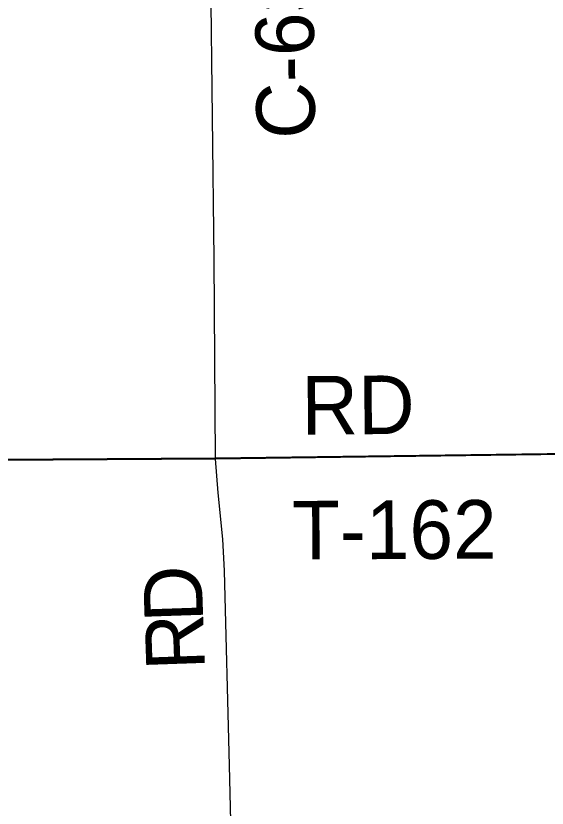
# Model space of a CAD drawing. Extents: x 0 to 34, y 0 to 22.
# Drawn here: x 6.756 to 7.272, y 14.874 to 15.642 of the extents above; entities that cross this region are included whole.
import ezdxf

# ---------------------------------------------------------------- set-up
doc = ezdxf.new("R2010")
doc.units = 0
for name, color, linetype in [('GM_X_Corporation', 7, 'Continuous'), ('GM_X_County_Road', 7, 'Continuous'), ('GM_X_County_Road_Text', 7, 'Continuous'), ('GM_X_Township_Road', 7, 'Continuous'), ('GM_X_Township_Road_Text', 7, 'Continuous')]:
    doc.layers.add(name, color=color, linetype=linetype)

msp = doc.modelspace()

# ---------------------------------------------------------------- linework, layer by layer
at = {"layer": 'GM_X_Corporation'}
msp.add_lwpolyline([(5.90994, 15.72564), (5.90994, 15.21376), (6.10258, 15.21454), (6.73943, 15.21199), (6.94963, 15.21339), (8.01532, 15.22729), (7.992, 16.45338)], dxfattribs=at)
msp.add_lwpolyline([(3.69009, 15.2048), (3.5209, 15.20411), (2.73663, 15.2014), (2.74225, 14.8151), (2.77525, 14.15375), (2.77611, 14.09996), (8.03831, 14.09996), (8.03504, 14.24979), (8.03488, 14.25722), (8.02966, 14.49633), (8.02618, 14.65547), (8.01532, 15.22729), (6.94963, 15.21339), (6.73943, 15.21199), (6.10258, 15.21454), (5.90994, 15.21376), (5.90994, 15.00852), (3.69009, 15.00852)], close=True, dxfattribs=at)
at = {"layer": 'GM_X_County_Road'}
for points in [[(6.94984, 15.21284), (6.94865, 15.40616), (6.94358, 15.81937), (6.93852, 16.22879), (6.93693, 16.45059), (6.93074, 16.82013), (6.92886, 17.07212)], [(7.0323, 14.09996), (6.98358, 14.22946), (6.97398, 14.46889), (6.9636, 14.91548), (6.95861, 15.10423), (6.95708, 15.13499), (6.95252, 15.1798), (6.94984, 15.21284)]]:
    msp.add_lwpolyline(points, dxfattribs=at)
at = {"layer": 'GM_X_Township_Road'}
msp.add_line((6.94984, 15.21284), (8.01553, 15.22674), dxfattribs=at)
msp.add_lwpolyline([(6.71506, 15.2201), (6.7165, 15.21866), (6.72295, 15.2141), (6.73964, 15.21144), (6.94984, 15.21284)], dxfattribs=at)

# ---------------------------------------------------------------- texts
at = {"layer": 'GM_X_County_Road_Text'}
for s, height, rotation, p in [('C-63', 0.056818, 90.68578, (7.04657, 15.52324)), ('D', 0.05682, 91.93101, (6.93804, 15.0554)), ('R', 0.05682, 92.00655, (6.93967, 15.00878))]:
    msp.add_text(s, height=height, rotation=rotation, dxfattribs=at).set_placement(p)
at = {"layer": 'GM_X_Township_Road_Text'}
for s, rotation, p in [('RD', 0.49366, (7.0335, 15.23607)), ('T-162', 0.2807, (7.02417, 15.11511))]:
    msp.add_text(s, height=0.056818, rotation=rotation, dxfattribs=at).set_placement(p)

doc.saveas('drawing.dxf')
